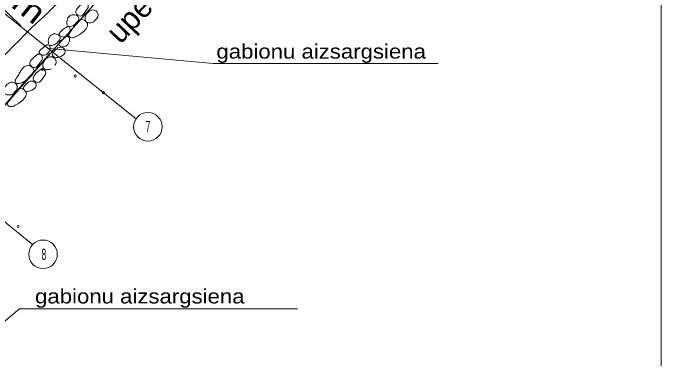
# Model space of a CAD drawing. Extents: x -1271.1 to -1218.8, y 769 to 838.3.
# Drawn here: x -1247.62 to -1218.85, y 793.48 to 808.82 of the extents above; entities that cross this region are included whole.
import ezdxf
from ezdxf.enums import TextEntityAlignment as Align

# ---------------------------------------------------------------- set-up
doc = ezdxf.new("R2010")
doc.units = 0
doc.header["$LTSCALE"] = 0.2
doc.linetypes.add('DOT_DASHED', pattern=[7.7, 5, -1.2, 0.3, -1.2])
for name, color, linetype, lineweight in [('1', 7, 'Continuous', 13), ('19', 7, 'Continuous', 13), ('6', 7, 'Continuous', 13), ('63', 7, 'Continuous', 13)]:
    doc.layers.add(name, color=color, linetype=linetype, lineweight=lineweight)
doc.layers.add('27', color=7, linetype='Continuous')

msp = doc.modelspace()

# ---------------------------------------------------------------- linework, layer by layer
at = {"layer": '1'}
for p, q in [((-1256.057, 815.213), (-1242.15, 804.124)), ((-1250.507, 811.376), (-1247.272, 808.252)), ((-1259.05, 808.547), (-1246.761, 798.528))]:
    msp.add_line(p, q, dxfattribs=at)
for centre in [(-1241.633, 803.7645), (-1246.2897, 798.0951)]:
    msp.add_circle(centre, 0.635, dxfattribs=at)
msp.add_spline([(-1235.8, 825.801), (-1237.913, 825.174), (-1239.203, 823.346), (-1241.709, 821.268), (-1246.557, 815.58), (-1256.526, 805.053), (-1260.592, 799.147), (-1261.416, 795.29), (-1262.742, 791.444), (-1262.206, 785.139)], degree=3, dxfattribs=at)
at = {"layer": '19'}
msp.add_spline([(-1253.457, 785.393), (-1253.726, 794.104), (-1251.637, 801.373), (-1250.122, 804.26), (-1247.608, 807.348), (-1239.437, 815.545), (-1236.508, 819.221), (-1228.799, 821.851), (-1223.357, 826.161), (-1220.079, 827.95)], degree=3, dxfattribs=at)
at = {"layer": '6'}
for centre in [(-1246.309, 806.3192), (-1244.862, 806.0262), (-1243.613, 805.2772), (-1247.3937, 799.3304)]:
    msp.add_circle(centre, 0.05, dxfattribs=at)
at = {"layer": '63'}
msp.add_line((-1218.845, 838.277), (-1218.845, 768.981), dxfattribs=at)
at = {"layer": '63', "linetype": 'DOT_DASHED', "lineweight": 25}
msp.add_lwpolyline([(-1254.918, 786.26), (-1254.605, 794.542), (-1253.865, 797.042), (-1252.437, 799.553), (-1250.698, 801.658), (-1245.95, 807.041), (-1239.139, 814.697), (-1235.363, 819.429), (-1232.239, 822.444), (-1231.619, 822.931), (-1231.44, 822.991), (-1229.31, 823.677), (-1223.125, 826.536)], dxfattribs=at)
at = {"layer": '63', "lineweight": 35}
msp.add_lwpolyline([(-1254.918, 786.26), (-1254.605, 794.542), (-1253.865, 797.042), (-1252.437, 799.553), (-1251.568, 800.606), (-1250.698, 801.658), (-1248.324, 804.35), (-1245.95, 807.041), (-1242.544, 810.869), (-1239.139, 814.697), (-1237.251, 817.063), (-1235.363, 819.429), (-1233.801, 820.936), (-1232.239, 822.444), (-1231.619, 822.931), (-1229.31, 823.677), (-1223.125, 826.536)], dxfattribs=at)
at = {"layer": '63'}
for points in [[(-1228.737, 806.576), (-1238.728, 806.576), (-1246.038, 807.247)], [(-1254.837, 789.362), (-1247.335, 795.673), (-1234.983, 795.673)]]:
    msp.add_lwpolyline(points, dxfattribs=at)
for points in [[(-1244.486, 809.285), (-1244.706, 809.1), (-1244.833, 808.831), (-1244.627, 808.688), (-1244.383, 808.924), (-1244.278, 809.118), (-1244.359, 809.265), (-1244.486, 809.285)], [(-1245.224, 808.299), (-1245.208, 808.552), (-1245.051, 808.722), (-1244.81, 808.717), (-1244.707, 808.621), (-1244.787, 808.404), (-1244.922, 808.285), (-1245.145, 808.226), (-1245.222, 808.25)], [(-1244.039, 808.449), (-1243.836, 808.728), (-1243.996, 808.949), (-1244.234, 808.902), (-1244.401, 808.695), (-1244.38, 808.43), (-1244.202, 808.387), (-1244.051, 808.418)], [(-1244.913, 807.745), (-1245.051, 807.727), (-1245.142, 807.812), (-1245.036, 808.028), (-1244.883, 808.3), (-1244.551, 808.527), (-1244.319, 808.358), (-1244.579, 807.921), (-1244.801, 807.787), (-1244.9, 807.732)], [(-1245.196, 808.231), (-1245.405, 808.088), (-1245.573, 807.853), (-1245.355, 807.753), (-1245.171, 807.862), (-1245.087, 808.097), (-1245.162, 808.214), (-1245.221, 808.214)], [(-1246.048, 807.449), (-1246.032, 807.702), (-1245.875, 807.872), (-1245.634, 807.867), (-1245.531, 807.771), (-1245.611, 807.554), (-1245.746, 807.435), (-1245.969, 807.376), (-1246.046, 807.4)], [(-1245.217, 807.794), (-1245.426, 807.651), (-1245.594, 807.416), (-1245.376, 807.316), (-1245.192, 807.425), (-1245.108, 807.66), (-1245.183, 807.777), (-1245.242, 807.777)], [(-1246.081, 807.424), (-1246.29, 807.281), (-1246.458, 807.046), (-1246.24, 806.946), (-1246.056, 807.055), (-1245.972, 807.29), (-1246.047, 807.407), (-1246.106, 807.407)], [(-1245.654, 807.276), (-1245.376, 807.261), (-1245.306, 807.1), (-1245.501, 806.892), (-1245.775, 806.856), (-1245.867, 806.94), (-1245.773, 807.145), (-1245.639, 807.263)], [(-1246.522, 806.99), (-1246.742, 806.805), (-1246.869, 806.536), (-1246.663, 806.393), (-1246.419, 806.629), (-1246.314, 806.823), (-1246.395, 806.97), (-1246.522, 806.99)], [(-1245.765, 806.481), (-1245.707, 806.647), (-1245.867, 806.868), (-1246.105, 806.821), (-1246.272, 806.614), (-1246.251, 806.349), (-1246.073, 806.306), (-1245.922, 806.337)], [(-1247.299, 805.709), (-1247.437, 805.691), (-1247.528, 805.776), (-1247.422, 805.992), (-1247.269, 806.264), (-1246.937, 806.491), (-1246.705, 806.322), (-1246.965, 805.885), (-1247.187, 805.751), (-1247.286, 805.696)], [(-1246.378, 806.328), (-1246.598, 806.143), (-1246.725, 805.874), (-1246.519, 805.731), (-1246.275, 805.967), (-1246.17, 806.161), (-1246.251, 806.308), (-1246.378, 806.328)], [(-1247.489, 805.353), (-1247.431, 805.519), (-1247.591, 805.74), (-1247.829, 805.693), (-1247.996, 805.486), (-1247.975, 805.221), (-1247.797, 805.178), (-1247.646, 805.209)], [(-1246.941, 805.774), (-1246.663, 805.759), (-1246.593, 805.598), (-1246.788, 805.39), (-1247.062, 805.354), (-1247.154, 805.438), (-1247.06, 805.643), (-1246.926, 805.761)], [(-1247.635, 804.682), (-1247.773, 804.664), (-1247.864, 804.749), (-1247.758, 804.965), (-1247.605, 805.237), (-1247.273, 805.464), (-1247.041, 805.295), (-1247.301, 804.858), (-1247.523, 804.724), (-1247.622, 804.669)]]:
    msp.add_spline(points, degree=3, dxfattribs=at)

# ---------------------------------------------------------------- texts
at = {"layer": '1', "width": 0.55}
for s, p in [('7', (-1241.728, 803.527)), ('8', (-1246.353, 797.848))]:
    msp.add_text(s, height=0.5, dxfattribs=at).set_placement(p)
at = {"layer": '27'}
msp.add_text('upe Íekava', height=1, rotation=46.796, dxfattribs=at).set_placement((-1242.855, 807.398))
at = {"layer": '63', "width": 1.25}
msp.add_text('7,8m', height=1, rotation=321.432, dxfattribs=at).set_placement((-1248.1252, 809.4158), align=Align.CENTER)
at = {"layer": '63', "width": 1.15}
for p in [(-1233.9375, 806.795), (-1241.9915, 795.91)]:
    msp.add_text('gabionu aizsargsiena', height=0.64, dxfattribs=at).set_placement(p, align=Align.CENTER)

doc.saveas('drawing.dxf')
